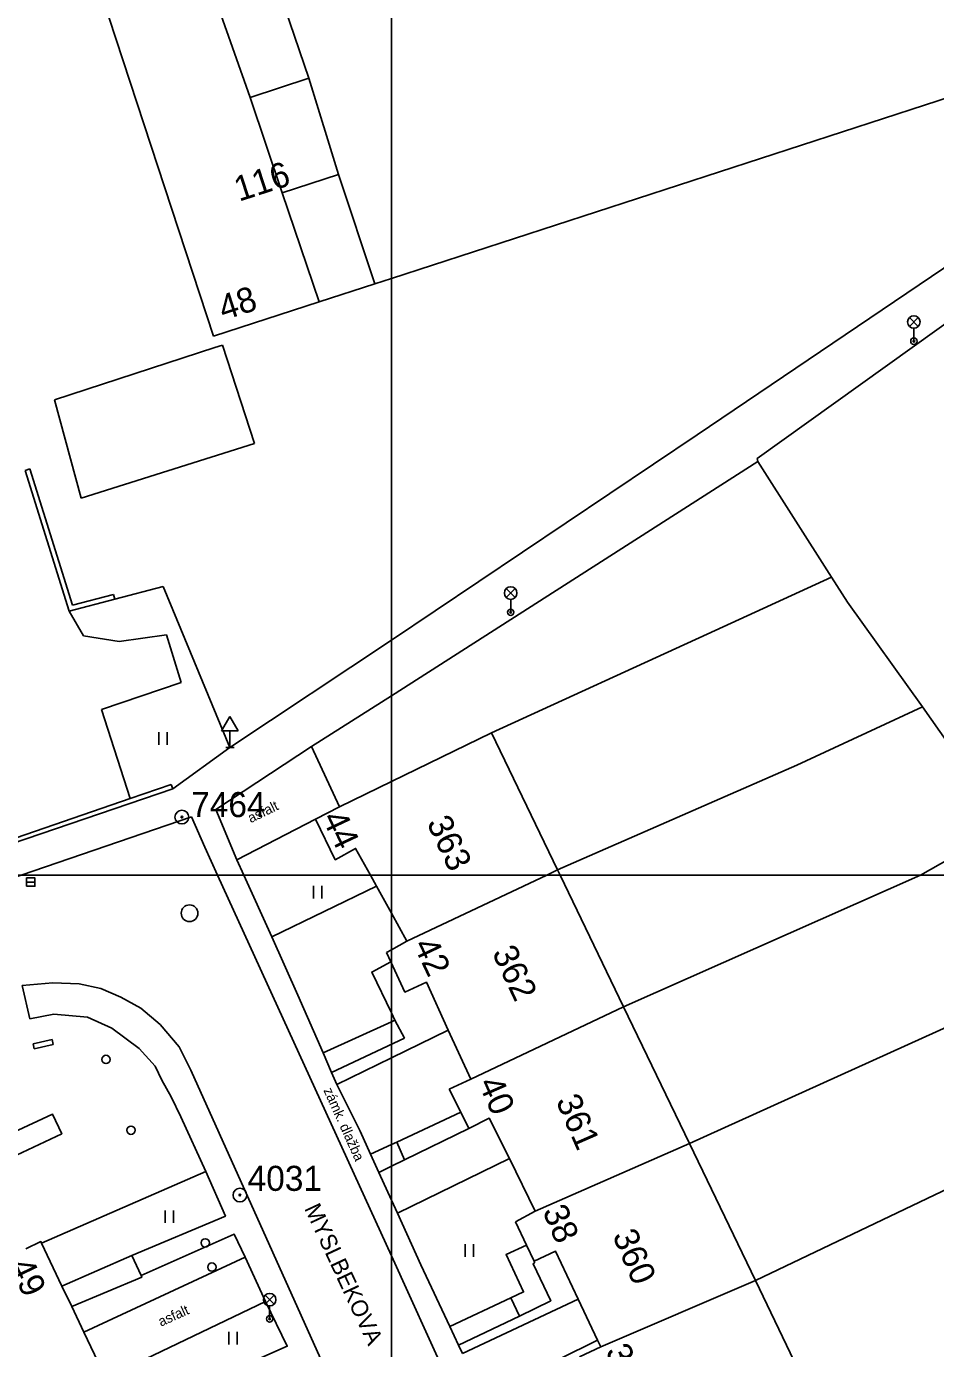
# Model space of a CAD drawing. Extents: x -493753 to -49290, y -1127285 to -112654.
# Drawn here: x -493146.9 to -493092.4, y -1127028.4 to -1126949.2 of the extents above; entities that cross this region are included whole.
import ezdxf

# ---------------------------------------------------------------- set-up
doc = ezdxf.new("R2010")
doc.units = 0
for name, color, linetype in [('Vrstva 10', 7, 'Continuous'), ('Vrstva 11', 7, 'Continuous'), ('Vrstva 24', 7, 'Continuous'), ('Vrstva 27', 7, 'Continuous'), ('Vrstva 28', 7, 'Continuous'), ('Vrstva 33', 7, 'Continuous'), ('Vrstva 34', 7, 'Continuous'), ('Vrstva 36', 7, 'Continuous'), ('Vrstva 40', 7, 'Continuous'), ('Vrstva 43', 7, 'Continuous'), ('Vrstva 44', 7, 'Continuous'), ('Vrstva 45', 7, 'Continuous'), ('Vrstva 5', 7, 'Continuous'), ('Vrstva 60', 7, 'Continuous'), ('Vrstva 63', 7, 'Continuous'), ('Vrstva 7', 7, 'Continuous'), ('Vrstva 8', 7, 'Continuous')]:
    doc.layers.add(name, color=color, linetype=linetype)

msp = doc.modelspace()

# ---------------------------------------------------------------- linework, layer by layer
at = {"layer": 'Vrstva 10'}
for p, q in [((-493146.96, -1126975.76), (-493146.67, -1126975.67)), ((-493146.96, -1126975.76), (-493144.32, -1126984.2)), ((-493146.67, -1126975.67), (-493144.12, -1126983.84)), ((-493144.12, -1126983.84), (-493141.66, -1126983.19)), ((-493141.58, -1126983.48), (-493141.66, -1126983.19)), ((-493144.32, -1126984.2), (-493141.58, -1126983.48)), ((-493143.46, -1126985.68), (-493144.32, -1126984.2)), ((-493141.32, -1126986.02), (-493143.46, -1126985.68)), ((-493138.48, -1126985.61), (-493141.32, -1126986.02)), ((-493137.6, -1126988.47), (-493138.48, -1126985.61)), ((-493142.38, -1126990.09), (-493137.6, -1126988.47)), ((-493140.65, -1126995.42), (-493142.38, -1126990.09)), ((-493179.35, -1127008.88), (-493138.11, -1126994.84)), ((-493138.2, -1126994.58), (-493140.65, -1126995.42)), ((-493138.2, -1126994.58), (-493138.11, -1126994.84)), ((-493140.65, -1126995.42), (-493179.43, -1127008.71)), ((-493136.98, -1126996.52), (-493178.78, -1127010.77)), ((-493136.18, -1126998.33), (-493135.42, -1127000)), ((-493135.42, -1127000), (-493125, -1127022.81)), ((-493146.67, -1127008.62), (-493145.24, -1127008.33)), ((-493145.24, -1127008.33), (-493143.22, -1127008.52)), ((-493143.22, -1127008.52), (-493141.76, -1127009.17)), ((-493141.76, -1127009.17), (-493140.11, -1127010.4)), ((-493140.11, -1127010.4), (-493139.17, -1127011.45)), ((-493139.17, -1127011.45), (-493138.77, -1127012.28)), ((-493121.43, -1127046.36), (-493137.02, -1127011.69)), ((-493138.77, -1127012.28), (-493138.2, -1127013.29)), ((-493138.2, -1127013.29), (-493137.63, -1127014.48)), ((-493137.63, -1127014.48), (-493136.12, -1127017.77)), ((-493125, -1127022.81), (-493115.54, -1127043.53)), ((-493116.45, -1127023.14), (-493116.42, -1127023.23)), ((-493113.81, -1127025.41), (-493120.74, -1127028.66)), ((-493120.97, -1127028.17), (-493117.32, -1127026.42)), ((-493119.56, -1127031.27), (-493112.64, -1127027.86))]:
    msp.add_line(p, q, dxfattribs=at)
for points in [[(-493129.78, -1126992.31), (-493135.53, -1126996.07)], [(-493136.98, -1126996.52), (-493136.18, -1126998.33)], [(-493135.53, -1126996.07), (-493134.27, -1126999.1)], [(-493133.85, -1127000), (-493134.27, -1126999.1), (-493129.55, -1126996.66)], [(-493125, -1127019.47), (-493125.76, -1127017.82), (-493126.26, -1127016.72), (-493126.88, -1127015.35), (-493128.27, -1127012.55), (-493128.59, -1127011.82), (-493129.09, -1127010.66), (-493130.6, -1127007.19), (-493132.16, -1127003.71), (-493133.85, -1127000)], [(-493125.9, -1127000.66), (-493132.16, -1127003.71)], [(-493125, -1127008.26), (-493126.18, -1127005.81), (-493125.04, -1127005.2)], [(-493141.22, -1127007.32), (-493142.41, -1127006.79), (-493143.72, -1127006.52), (-493145.3, -1127006.45), (-493147.14, -1127006.61)], [(-493147.14, -1127006.61), (-493146.67, -1127008.62)], [(-493137.02, -1127011.69), (-493137.72, -1127010.29), (-493138.87, -1127008.95), (-493140.02, -1127007.98), (-493141.22, -1127007.32)], [(-493124.79, -1127008.69), (-493125, -1127008.26)], [(-493125, -1127008.79), (-493124.79, -1127008.69)], [(-493124.79, -1127008.69), (-493124.21, -1127009.78)], [(-493129.09, -1127010.66), (-493125, -1127008.79)], [(-493121.59, -1127009.29), (-493125, -1127010.95)], [(-493128.59, -1127011.82), (-493124.21, -1127009.78)], [(-493125, -1127010.95), (-493128.27, -1127012.55)], [(-493124.68, -1127016.01), (-493120.84, -1127014.2)], [(-493125, -1127017.45), (-493124.21, -1127017.06), (-493120.35, -1127015.18)], [(-493126.26, -1127016.72), (-493125, -1127016.15)], [(-493125, -1127016.15), (-493124.68, -1127016.01)], [(-493145.97, -1127022.06), (-493136.12, -1127017.77), (-493134.95, -1127020.43), (-493140.55, -1127022.79)], [(-493125.76, -1127017.82), (-493125, -1127017.45)], [(-493121.5, -1127027.05), (-493123.23, -1127023.36), (-493124.64, -1127020.26), (-493125, -1127019.47)], [(-493144.16, -1127025.85), (-493139.96, -1127024.1), (-493140, -1127024), (-493134.42, -1127021.52), (-493133.76, -1127022.9)], [(-493116.91, -1127022.17), (-493118.13, -1127022.74), (-493117.08, -1127024.97), (-493117.84, -1127025.33), (-493121.5, -1127027.05)], [(-493140.55, -1127022.79), (-493144.75, -1127024.62)], [(-493133.76, -1127022.9), (-493143.43, -1127027.38)], [(-493133.76, -1127022.9), (-493132.54, -1127025.54)], [(-493117.32, -1127026.42), (-493115.45, -1127025.5), (-493116.51, -1127023.29), (-493116.42, -1127023.23)], [(-493141.18, -1127029.68), (-493132.54, -1127025.54), (-493131.24, -1127028.23), (-493135.8, -1127030.24)], [(-493120.74, -1127028.66), (-493120.97, -1127028.17), (-493121.5, -1127027.05)]]:
    msp.add_lwpolyline(points, dxfattribs=at)
at = {"layer": 'Vrstva 11'}
for points in [[(-493129.94, -1126952.26), (-493133.95, -1126940.54)], [(-493137.1, -1126943.12), (-493133.47, -1126953.43)], [(-493133.47, -1126953.43), (-493129.94, -1126952.26)], [(-493128.18, -1126958.03), (-493129.94, -1126952.26)], [(-493131.54, -1126959.14), (-493133.47, -1126953.43)], [(-493128.18, -1126958.03), (-493131.54, -1126959.14)], [(-493126, -1126964.58), (-493128.18, -1126958.03)], [(-493131.54, -1126959.14), (-493129.32, -1126965.66)], [(-493135.13, -1126968.25), (-493135.59, -1126968.4)], [(-493135.13, -1126968.25), (-493133.21, -1126974.14)], [(-493145.19, -1126971.54), (-493135.59, -1126968.4)], [(-493143.59, -1126977.43), (-493145.19, -1126971.54)], [(-493133.21, -1126974.14), (-493143.59, -1126977.43)], [(-493106.07, -1126985.58), (-493098.61, -1126982.15)], [(-493097.66, -1126983.65), (-493093.16, -1126989.93)], [(-493118.99, -1126991.49), (-493106.07, -1126985.58)], [(-493100.69, -1126993.42), (-493093.16, -1126989.93)], [(-493093.16, -1126989.93), (-493091.6, -1126992.14)], [(-493115.04, -1126999.69), (-493100.69, -1126993.42)], [(-493093.28, -1127000), (-493088.34, -1126997.22)], [(-493111.09, -1127007.89), (-493093.28, -1127000)], [(-493107.13, -1127016.09), (-493083.26, -1127005.28)], [(-493103.18, -1127024.29), (-493078.58, -1127012.54)], [(-493124.68, -1127016.01), (-493124.21, -1127017.06)], [(-493117.93, -1127016.99), (-493124.64, -1127020.26)], [(-493140.55, -1127022.79), (-493140, -1127024)], [(-493117.32, -1127026.42), (-493117.84, -1127025.33)]]:
    msp.add_lwpolyline(points, dxfattribs=at)
at = {"layer": 'Vrstva 24'}
for p, q in [((-493146.47, -1127010.11), (-493145.34, -1127009.86)), ((-493146.41, -1127010.42), (-493146.47, -1127010.11)), ((-493145.27, -1127010.15), (-493146.41, -1127010.42)), ((-493145.34, -1127009.86), (-493145.27, -1127010.15))]:
    msp.add_line(p, q, dxfattribs=at)
at = {"layer": 'Vrstva 27'}
msp.add_line((-493146.87, -1127000.42), (-493146.37, -1127000.42), dxfattribs=at)
msp.add_lwpolyline([(-493146.87, -1127000.67), (-493146.37, -1127000.67), (-493146.37, -1127000.17), (-493146.87, -1127000.17)], close=True, dxfattribs=at)
msp.add_circle((-493137.1, -1127002.29), 0.5, dxfattribs=at)
at = {"layer": 'Vrstva 28'}
for centre in [(-493142.11, -1127011.05), (-493140.61, -1127015.29), (-493136.16, -1127022.04), (-493135.76, -1127023.49)]:
    msp.add_circle(centre, 0.25, dxfattribs=at)
at = {"layer": 'Vrstva 33'}
for p, q in [((-493093.945, -1126966.605), (-493093.415, -1126967.135)), ((-493093.945, -1126967.135), (-493093.415, -1126966.605)), ((-493093.68, -1126968.02), (-493093.68, -1126967.245)), ((-493118.115, -1126982.845), (-493117.585, -1126983.375)), ((-493118.115, -1126983.375), (-493117.585, -1126982.845)), ((-493117.85, -1126984.26), (-493117.85, -1126983.485)), ((-493132.565, -1127025.175), (-493132.035, -1127025.705)), ((-493132.565, -1127025.705), (-493132.035, -1127025.175)), ((-493132.3, -1127026.59), (-493132.3, -1127025.815))]:
    msp.add_line(p, q, dxfattribs=at)
for centre, radius in [((-493093.68, -1126966.87), 0.375), ((-493093.68, -1126968.02), 0.19), ((-493093.68, -1126968.02), 0.05), ((-493117.85, -1126983.11), 0.375), ((-493117.85, -1126984.26), 0.19), ((-493117.85, -1126984.26), 0.05), ((-493132.3, -1127025.44), 0.375), ((-493132.3, -1127026.59), 0.19), ((-493132.3, -1127026.59), 0.05)]:
    msp.add_circle(centre, radius, dxfattribs=at)
at = {"layer": 'Vrstva 34'}
for p, q in [((-493135.18, -1126991.36), (-493134.68, -1126990.51)), ((-493134.68, -1126990.51), (-493134.18, -1126991.36)), ((-493135.18, -1126991.36), (-493134.18, -1126991.36)), ((-493134.68, -1126992.36), (-493134.68, -1126991.36)), ((-493134.93, -1126992.36), (-493134.43, -1126992.36))]:
    msp.add_line(p, q, dxfattribs=at)
at = {"layer": 'Vrstva 36'}
for p, q in [((-493138.94, -1126992.2), (-493138.94, -1126991.45)), ((-493138.44, -1126992.2), (-493138.44, -1126991.45)), ((-493129.66, -1127001.4), (-493129.66, -1127000.65)), ((-493129.16, -1127001.4), (-493129.16, -1127000.65)), ((-493138.57, -1127020.84), (-493138.57, -1127020.09)), ((-493138.07, -1127020.84), (-493138.07, -1127020.09)), ((-493120.57, -1127022.87), (-493120.57, -1127022.12)), ((-493120.07, -1127022.87), (-493120.07, -1127022.12)), ((-493134.74, -1127028.12), (-493134.74, -1127027.37)), ((-493134.24, -1127028.12), (-493134.24, -1127027.37))]:
    msp.add_line(p, q, dxfattribs=at)
at = {"layer": 'Vrstva 5'}
for p, q in [((-493143.04, -1126945.24), (-493135.67, -1126967.73)), ((-493125, -1126964.26), (-493079.9, -1126949.6)), ((-493121.53, -1127012.82), (-493120.24, -1127012.23))]:
    msp.add_line(p, q, dxfattribs=at)
for points in [[(-493126, -1126964.58), (-493125, -1126964.26)], [(-493129.32, -1126965.66), (-493126, -1126964.58)], [(-493135.67, -1126967.73), (-493129.32, -1126965.66)], [(-493118.99, -1126991.49), (-493125, -1126994.4)], [(-493115.04, -1126999.69), (-493118.99, -1126991.49)], [(-493125, -1126994.4), (-493128.12, -1126995.92)], [(-493128.12, -1126995.92), (-493129.55, -1126996.66), (-493128.37, -1126999.09), (-493127.15, -1126998.41), (-493126.26, -1127000)], [(-493126.26, -1127000), (-493125.9, -1127000.66), (-493125, -1127002.28)], [(-493115.69, -1127000), (-493124.07, -1127003.96)], [(-493115.04, -1126999.69), (-493115.69, -1127000)], [(-493114.89, -1127000), (-493115.04, -1126999.69)], [(-493111.09, -1127007.89), (-493114.89, -1127000)], [(-493125, -1127002.28), (-493124.07, -1127003.96)], [(-493124.07, -1127003.96), (-493125, -1127004.48)], [(-493125, -1127004.48), (-493125.3, -1127004.64)], [(-493125.3, -1127004.64), (-493125.04, -1127005.2)], [(-493125.04, -1127005.2), (-493124.19, -1127007.01), (-493122.9, -1127006.42), (-493121.59, -1127009.29), (-493120.24, -1127012.23)], [(-493111.09, -1127007.89), (-493120.24, -1127012.23)], [(-493107.13, -1127016.09), (-493111.09, -1127007.89)], [(-493121.53, -1127012.82), (-493120.84, -1127014.2), (-493120.35, -1127015.18), (-493119.13, -1127014.57), (-493117.93, -1127016.99), (-493116.38, -1127020.14)], [(-493149.19, -1127017.59), (-493144.76, -1127015.5), (-493145.32, -1127014.32), (-493149.76, -1127016.39)], [(-493107.13, -1127016.09), (-493116.38, -1127020.14)], [(-493103.18, -1127024.29), (-493107.13, -1127016.09)], [(-493116.38, -1127020.14), (-493117.57, -1127020.78)], [(-493117.57, -1127020.78), (-493116.91, -1127022.17), (-493116.45, -1127023.14), (-493115.17, -1127022.53), (-493113.81, -1127025.41), (-493112.64, -1127027.86), (-493112.45, -1127028.26)], [(-493146.91, -1127022.39), (-493146.01, -1127021.96), (-493145.97, -1127022.06), (-493144.75, -1127024.62), (-493144.16, -1127025.85), (-493143.43, -1127027.38), (-493142.15, -1127030.07)], [(-493103.18, -1127024.29), (-493112.45, -1127028.26)], [(-493099.23, -1127032.5), (-493103.18, -1127024.29)], [(-493112.45, -1127028.26), (-493113.72, -1127028.86)]]:
    msp.add_lwpolyline(points, dxfattribs=at)
at = {"layer": 'Vrstva 60'}
for points in [[(-493659.148, -1127000), (-493125, -1127000), (-493125, -1126587.478)], [(-493125, -1126587.478), (-493125, -1127000), (-492991.121, -1127000)], [(-493125, -1127069.371), (-493125, -1127000), (-493659.148, -1127000)], [(-492991.121, -1127000), (-493125, -1127000), (-493125, -1127069.371)]]:
    msp.add_lwpolyline(points, dxfattribs=at)
at = {"layer": 'Vrstva 63'}
for centre, radius in [((-493137.56, -1126996.53), 0.412), ((-493137.56, -1126996.53), 0.05), ((-493134.08, -1127019.17), 0.412), ((-493134.08, -1127019.17), 0.05)]:
    msp.add_circle(centre, radius, dxfattribs=at)
at = {"layer": 'Vrstva 7'}
for p, q in [((-493138.68, -1126982.72), (-493141.58, -1126983.48)), ((-493134.68, -1126992.36), (-493138.68, -1126982.72)), ((-493134.68, -1126992.36), (-493138.11, -1126994.84))]:
    msp.add_line(p, q, dxfattribs=at)
for points in [[(-493074.04, -1126951.6), (-493078.57, -1126954.66), (-493106.67, -1126973.64), (-493125, -1126985.93)], [(-493103.04, -1126975.22), (-493103.07, -1126975.05), (-493081.4, -1126959.54)], [(-493125, -1126989.26), (-493103.04, -1126975.22)], [(-493103.04, -1126975.22), (-493098.61, -1126982.15), (-493097.66, -1126983.65)], [(-493125, -1126985.93), (-493134.68, -1126992.36)], [(-493129.78, -1126992.31), (-493125, -1126989.26)]]:
    msp.add_lwpolyline(points, dxfattribs=at)
at = {"layer": 'Vrstva 8'}
msp.add_lwpolyline([(-493129.78, -1126992.31), (-493128.12, -1126995.92)], dxfattribs=at)

# ---------------------------------------------------------------- texts
at = {"layer": 'Vrstva 40'}
for s, rotation, p in [('asfalt', 26.0126, (-493133.432, -1126996.899)), ('zámk. dlažba', 294.21194, (-493129.085, -1127012.891)), ('asfalt', 24.49805, (-493138.813, -1127027.063))]:
    msp.add_text(s, height=0.6, rotation=rotation, dxfattribs=at).set_placement(p)
at = {"layer": 'Vrstva 43'}
for s, rotation, p in [('116', 18.00335, (-493134.131, -1126959.67)), ('363', 295.30524, (-493122.908, -1126996.873)), ('362', 295.35075, (-493118.99, -1127004.654)), ('361', 293.64205, (-493115.165, -1127013.527)), ('360', 293.16054, (-493111.77, -1127021.593))]:
    msp.add_text(s, height=1.5, rotation=rotation, dxfattribs=at).set_placement(p)
at = {"layer": 'Vrstva 44'}
for s, rotation, p in [('48', 17.72957, (-493135.067, -1126966.786)), ('44', 295.30524, (-493129.183, -1126996.575)), ('42', 295.35075, (-493123.709, -1127004.188)), ('40', 293.64205, (-493119.811, -1127012.466)), ('38', 293.16054, (-493115.962, -1127020.134)), ('49', 295.50032, (-493147.946, -1127023.383)), ('36', 295.7329, (-493112.194, -1127028.52))]:
    msp.add_text(s, height=1.5, rotation=rotation, dxfattribs=at).set_placement(p)
at = {"layer": 'Vrstva 45'}
msp.add_text('MYSLBEKOVA', height=1, rotation=295.02516, dxfattribs=at).set_placement((-493130.239, -1127019.968))
at = {"layer": 'Vrstva 63'}
for s, p in [(' 7464', (-493137.56, -1126996.53)), ('4031', (-493133.62, -1127018.92))]:
    msp.add_text(s, height=1.5, dxfattribs=at).set_placement(p)

doc.saveas('drawing.dxf')
